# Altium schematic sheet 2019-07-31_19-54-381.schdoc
size 226 x 140 mm; SheetNumber: 1; SheetTotal: 1
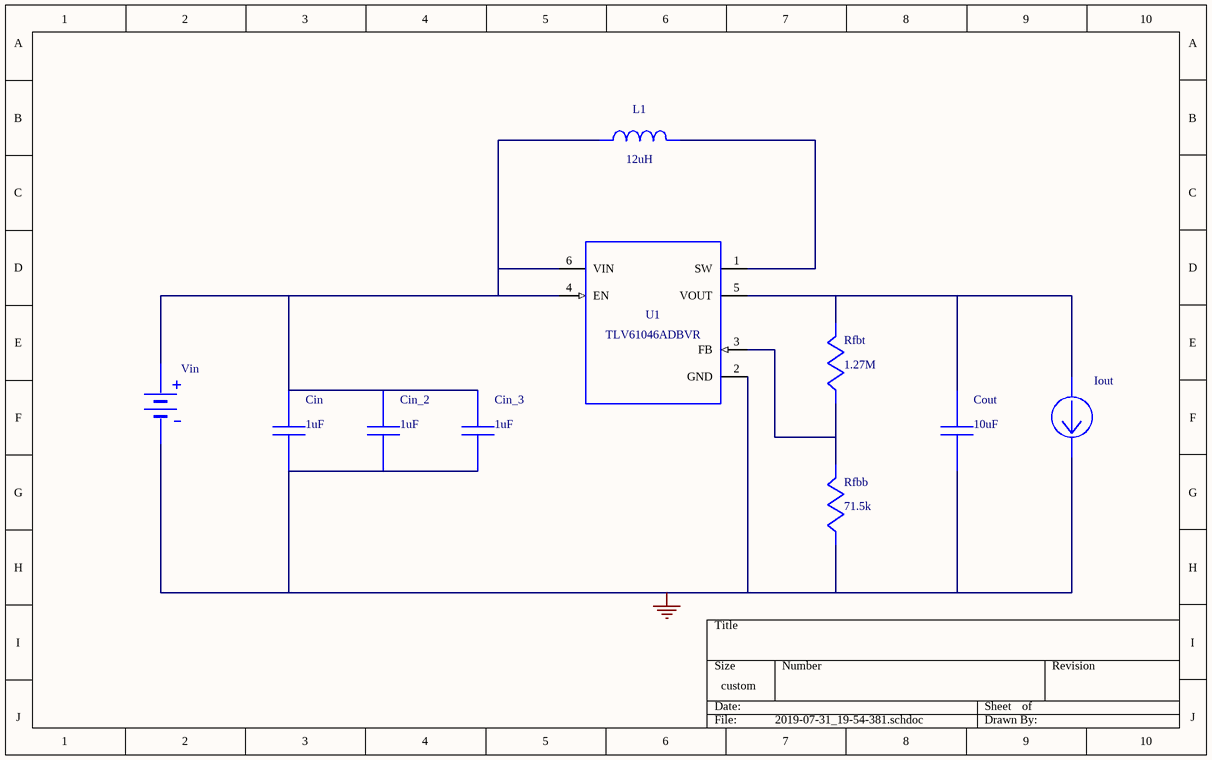
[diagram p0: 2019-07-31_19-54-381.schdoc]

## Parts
Cin  value 1uF  (hidden comment: C0603C105K8PACTU)
Cin_2  value 1uF  (hidden comment: C0603C105K8PACTU)
Cin_3  value 1uF  (hidden comment: C0603C105K8PACTU)
Cout  value 10uF  (hidden comment: CL32B106KBJNNWE)
Iout  WB_CURRENT_LOAD  (value not drawn)
L1  value 12uH  (hidden comment: NPI43C120MTRF)
Rfbb  value 71.5k  (hidden comment: CRCW040271K5FKED)
Rfbt  value 1.27M  (hidden comment: CRCW04021M27FKED)
U1  TLV61046ADBVR
Vin  WB_BATTERY  (value not drawn)

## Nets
0: Cin.2 Cin_2.2 Cin_3.2 Cout.2 Iout.2(-) Rfbb.2 U1.2(GND) Vin.2(-)
NetCin_1: Cin.1 Cin_2.1 Cin_3.1 L1.1 U1.4(EN) U1.6(VIN) Vin.1(+)
NetCout_1: Cout.1 Iout.1(+) Rfbt.1 U1.5(VOUT)
NetL1_2: L1.2 U1.1(SW)
NetRfbb_1: Rfbb.1 Rfbt.2 U1.3(FB)

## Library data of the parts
Cin Cin_2 Cin_3 = C0603C105K8PACTU: Manufacturer Name: Kemet
Cout = CL32B106KBJNNWE: Manufacturer Name: Samsung Electro-Mechanics
L1 = NPI43C120MTRF: Manufacturer Name: NIC Components
Rfbb = CRCW040271K5FKED: Manufacturer Name: Vishay-Dale
Rfbt = CRCW04021M27FKED: Manufacturer Name: Vishay-Dale
U1 = TLV61046ADBVR: Manufacturer Name: Texas Instruments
